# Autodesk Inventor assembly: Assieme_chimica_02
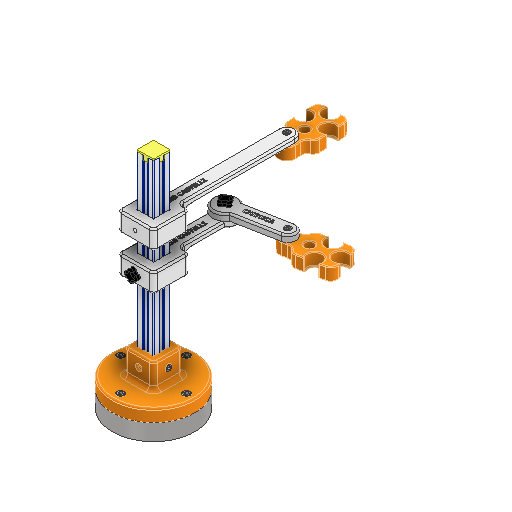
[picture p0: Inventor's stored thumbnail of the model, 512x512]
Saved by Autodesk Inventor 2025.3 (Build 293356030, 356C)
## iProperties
Created: 2025-09
Part Number: Assieme_chimica_02
Document SubType Name: Assembly
Designer: Ryzen5700u
Author: Ryzen5700u
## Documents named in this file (15)
- C:\Users\R5800u\Desktop\chimica5\Assieme_chimica_02.iam
- C:\Users\R5800u\Desktop\chimica5\tslot-20x20-3_MIR1.ipt
- C:\Users\R5800u\Desktop\chimica5\base_ferro.ipt
- C:\Users\R5800u\Desktop\chimica5\braccio.ipt
- C:\Users\R5800u\Desktop\chimica5\tappo_2020.ipt
- C:\Users\R5800u\Desktop\chimica5\vite_blocco.ipt
- C:\Users\R5800u\Desktop\chimica5\porta_sensore.ipt
- C:\Users\R5800u\Documents\Inventor\Content Center Files\R2025\it-IT\AS 1420\AS 1420 - 1973 - M5 x 20.ipt
- C:\Users\R5800u\Documents\Inventor\Content Center Files\R2025\it-IT\AS 1112 (2)\AS 1112 - M4  Tipo 5.ipt
- C:\Users\R5800u\Desktop\chimica5\AS 1420 - 1973 - M4 x 8.ipt
- C:\Users\R5800u\Desktop\chimica5\Slider T-Nut for 2020 - M4.ipt
- C:\Users\R5800u\Desktop\chimica5\base_petg2.ipt
- C:\Users\R5800u\Desktop\chimica5\braccio2.ipt
- C:\Users\R5800u\Documents\Inventor\Content Center Files\R2025\it-IT\AS 1420\AS 1420 - 1973 - M4 x 20.ipt
- C:\Users\R5800u\Desktop\chimica5\braccio_fisso.ipt
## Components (22 placed, 14 different names)
1. tslot-20x20-3_MIR1:1
2. base_petg2:1
3. base_ferro:1 — Allineato:6
4. braccio:1
5. tappo_2020:1 — Allineato:8
6. vite_blocco:1 — Allineato:9, Coincidente:22
7. porta_sensore:1 — Rotazionale:8, Angolo:2
8. AS 1420 - Metrico M5 x 20:1 — Coincidente:6
9. AS 1420 - Metrico M5 x 20:2 — Coincidente:8
10. AS 1420 - Metrico M5 x 20:3 — Coincidente:10
11. AS 1420 - Metrico M5 x 20:4 — Coincidente:12
12. AS 1112 (2) - Metrico M4  Tipo 5:1
13. AS 1112 (2) - Metrico M4  Tipo 5:2
14. AS 1420 - Metrico M4 x 8:4 — Rotazionale:4
15. AS 1420 - Metrico M4 x 20:1 — Rotazionale:7
16. Slider T-Nut for 2020 - M4:1 — Angolo:1, Coincidente:19, Coincidente:20
17. AS 1420 - Metrico M4 x 8:5 — Rotazionale:5
18. braccio2:1 — Coincidente:26, Coincidente:27, Rotazionale:6, Rotazionale:7, Rotazionale:8, Angolo:2
19. vite_blocco:2 — Rotazionale:6
20. braccio_fisso:1 — Coincidente:28, Coincidente:29, Rotazionale:9, Rotazionale:10
21. porta_sensore:2 — Rotazionale:9
22. AS 1420 - Metrico M4 x 20:2 — Rotazionale:10
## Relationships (23: Mate 11, RevoluteJoint 7, Flush 3, Angle 2)
- Allineato:6 [Flush]: base_ferro:1
- Allineato:8 [Flush]: tappo_2020:1
- Allineato:9 [Flush]: vite_blocco:1
- Coincidente:6 [Mate]: AS 1420 - Metrico M5 x 20:1
- Coincidente:8 [Mate]: AS 1420 - Metrico M5 x 20:2
- Coincidente:10 [Mate]: AS 1420 - Metrico M5 x 20:3
- Coincidente:12 [Mate]: AS 1420 - Metrico M5 x 20:4
- Angolo:1 [Angle]: Slider T-Nut for 2020 - M4:1
- Coincidente:19 [Mate]: Slider T-Nut for 2020 - M4:1
- Coincidente:20 [Mate]: Slider T-Nut for 2020 - M4:1
- Coincidente:22 [Mate]: vite_blocco:1
- Rotazionale:4 [RevoluteJoint]: AS 1420 - Metrico M4 x 8:4
- Rotazionale:5 [RevoluteJoint]: AS 1420 - Metrico M4 x 8:5
- Coincidente:26 [Mate]: braccio2:1
- Coincidente:27 [Mate]: braccio2:1
- Rotazionale:6 [RevoluteJoint]: braccio2:1 ↔ vite_blocco:2
- Rotazionale:7 [RevoluteJoint]: AS 1420 - Metrico M4 x 20:1 ↔ braccio2:1
- Rotazionale:8 [RevoluteJoint]: porta_sensore:1 ↔ braccio2:1
- Angolo:2 [Angle]: porta_sensore:1 ↔ braccio2:1
- Coincidente:28 [Mate]: braccio_fisso:1
- Coincidente:29 [Mate]: braccio_fisso:1
- Rotazionale:9 [RevoluteJoint]: braccio_fisso:1 ↔ porta_sensore:2
- Rotazionale:10 [RevoluteJoint]: braccio_fisso:1 ↔ AS 1420 - Metrico M4 x 20:2
